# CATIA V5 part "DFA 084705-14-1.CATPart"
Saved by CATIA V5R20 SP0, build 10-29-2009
Part number: DFA 084705-14-1
Revision: ANY
Definition: UNKNOWN
Nomenclature: DFA 084705-14-1
Source: Unknown
Bounding box of the stored display mesh (mm): x -3.98 to 3.804, y -10 to 10, z -4 to 4
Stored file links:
  C:\Users\Utente\Desktop\IO LAVORO\3D X SITO CF\CUMSA\3D files FA\FA 084705-21\DFA 084705-14-1.CATPart
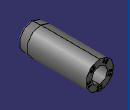
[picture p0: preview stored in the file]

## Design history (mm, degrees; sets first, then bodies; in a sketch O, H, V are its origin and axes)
Body1 "Cortar-Extruir5" (main body)
  Solid1: solid without history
